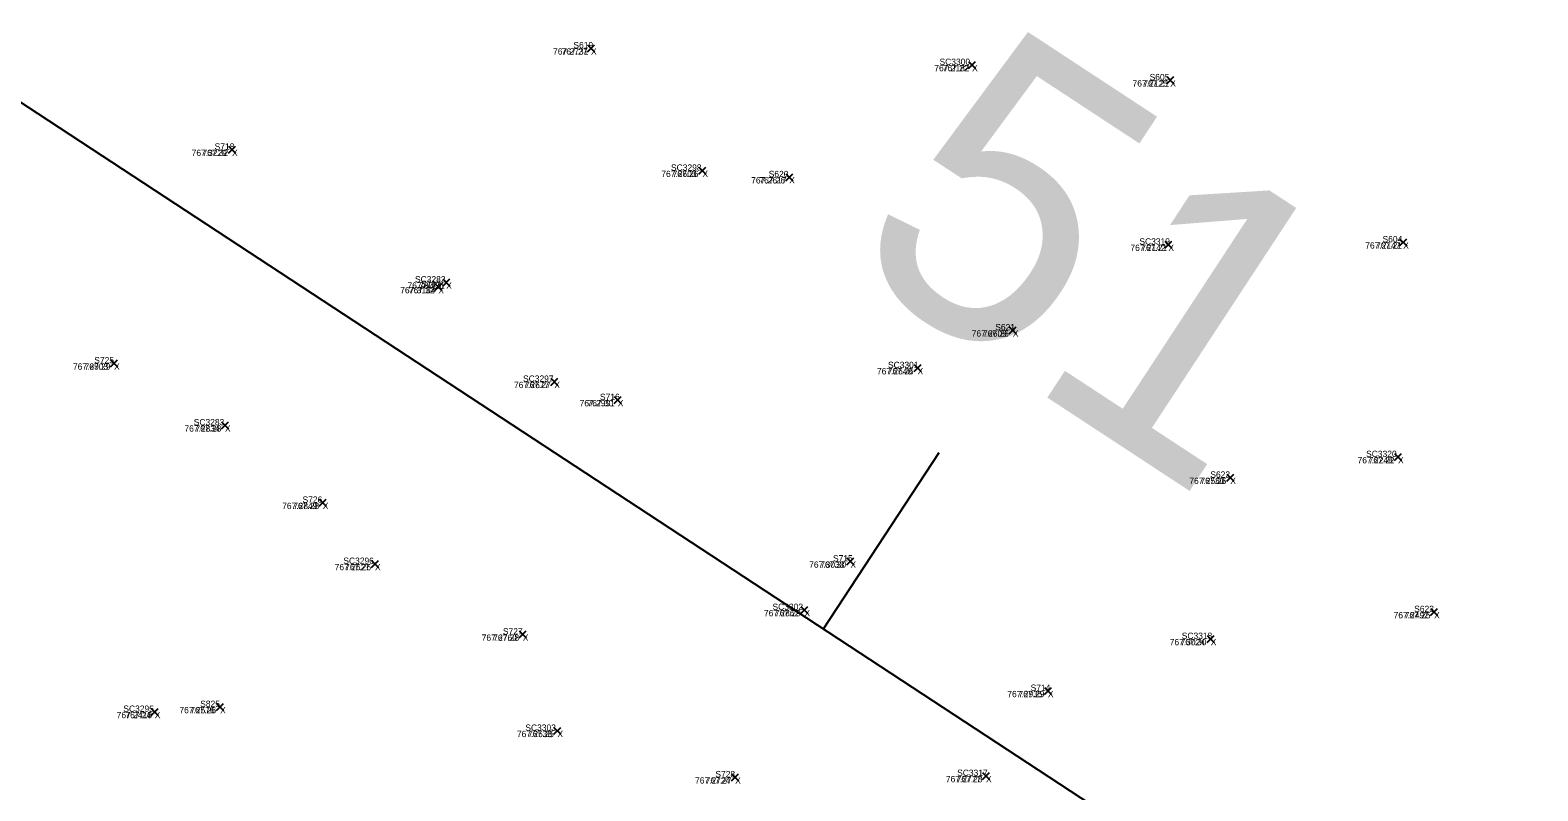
# Model space of a CAD drawing. Extents: x 1845019 to 1877956, y 680444 to 701081.
# Drawn here: x 1857724.6 to 1857738.9, y 694233.43 to 694240.65 of the extents above; entities that cross this region are included whole.
import ezdxf

# ---------------------------------------------------------------- set-up
doc = ezdxf.new("R2010")
doc.units = 0
for name, color, linetype in [('SV_X_CL_Survey_20', 7, 'Continuous'), ('SV_X_Random_Point', 7, 'Continuous'), ('SV_X_Text_Comment', 7, 'Continuous'), ('SV_X_Text_Elevation', 7, 'Continuous'), ('SV_X_Text_Name', 7, 'Continuous')]:
    doc.layers.add(name, color=color, linetype=linetype)

msp = doc.modelspace()

# ---------------------------------------------------------------- linework, layer by layer
at = {"layer": 'SV_X_CL_Survey_20'}
for p, q in [((1856038.267, 695346.314), (1858797.327, 693536.085)), ((1857732.122, 694234.97), (1857733.219, 694236.642))]:
    msp.add_line(p, q, dxfattribs=at)
at = {"layer": 'SV_X_Random_Point'}
for p, q in [((1857729.884, 694240.445), (1857729.95, 694240.512)), ((1857729.884, 694240.512), (1857729.95, 694240.445)), ((1857729.884, 694240.445), (1857729.95, 694240.512)), ((1857729.884, 694240.512), (1857729.95, 694240.445)), ((1857733.5, 694240.287), (1857733.566, 694240.354)), ((1857733.5, 694240.354), (1857733.566, 694240.287)), ((1857733.5, 694240.287), (1857733.566, 694240.354)), ((1857733.5, 694240.354), (1857733.566, 694240.287)), ((1857735.38, 694240.143), (1857735.447, 694240.21)), ((1857735.38, 694240.21), (1857735.447, 694240.143)), ((1857735.38, 694240.143), (1857735.447, 694240.21)), ((1857735.38, 694240.21), (1857735.447, 694240.143)), ((1857726.478, 694239.483), (1857726.544, 694239.55)), ((1857726.478, 694239.55), (1857726.544, 694239.483)), ((1857726.478, 694239.483), (1857726.544, 694239.55)), ((1857726.478, 694239.55), (1857726.544, 694239.483)), ((1857730.94, 694239.284), (1857731.007, 694239.35)), ((1857730.94, 694239.35), (1857731.007, 694239.284)), ((1857730.94, 694239.284), (1857731.007, 694239.35)), ((1857730.94, 694239.35), (1857731.007, 694239.284)), ((1857731.764, 694239.222), (1857731.831, 694239.289)), ((1857731.764, 694239.289), (1857731.831, 694239.222)), ((1857731.764, 694239.222), (1857731.831, 694239.289)), ((1857731.764, 694239.289), (1857731.831, 694239.222)), ((1857735.361, 694238.583), (1857735.428, 694238.649)), ((1857735.361, 694238.649), (1857735.428, 694238.583)), ((1857735.361, 694238.583), (1857735.428, 694238.649)), ((1857735.361, 694238.649), (1857735.428, 694238.583)), ((1857737.589, 694238.605), (1857737.656, 694238.671)), ((1857737.589, 694238.671), (1857737.656, 694238.605)), ((1857737.589, 694238.605), (1857737.656, 694238.671)), ((1857737.589, 694238.671), (1857737.656, 694238.605)), ((1857728.435, 694238.179), (1857728.502, 694238.246)), ((1857728.435, 694238.246), (1857728.502, 694238.179)), ((1857728.435, 694238.179), (1857728.502, 694238.246)), ((1857728.435, 694238.246), (1857728.502, 694238.179)), ((1857728.51, 694238.223), (1857728.577, 694238.29)), ((1857728.51, 694238.29), (1857728.577, 694238.223)), ((1857728.51, 694238.223), (1857728.577, 694238.29)), ((1857728.51, 694238.29), (1857728.577, 694238.223)), ((1857733.886, 694237.77), (1857733.952, 694237.836)), ((1857733.886, 694237.836), (1857733.952, 694237.77)), ((1857733.886, 694237.77), (1857733.952, 694237.836)), ((1857733.886, 694237.836), (1857733.952, 694237.77)), ((1857725.358, 694237.455), (1857725.425, 694237.522)), ((1857725.358, 694237.522), (1857725.425, 694237.455)), ((1857725.358, 694237.455), (1857725.425, 694237.522)), ((1857725.358, 694237.522), (1857725.425, 694237.455)), ((1857732.982, 694237.411), (1857733.049, 694237.477)), ((1857732.982, 694237.477), (1857733.049, 694237.411)), ((1857732.982, 694237.411), (1857733.049, 694237.477)), ((1857732.982, 694237.477), (1857733.049, 694237.411)), ((1857729.536, 694237.28), (1857729.603, 694237.347)), ((1857729.536, 694237.347), (1857729.603, 694237.28)), ((1857729.536, 694237.28), (1857729.603, 694237.347)), ((1857729.536, 694237.347), (1857729.603, 694237.28)), ((1857730.137, 694237.108), (1857730.204, 694237.175)), ((1857730.137, 694237.175), (1857730.204, 694237.108)), ((1857730.137, 694237.108), (1857730.204, 694237.175)), ((1857730.137, 694237.175), (1857730.204, 694237.108)), ((1857726.411, 694236.868), (1857726.477, 694236.935)), ((1857726.411, 694236.935), (1857726.477, 694236.868)), ((1857726.411, 694236.868), (1857726.477, 694236.935)), ((1857726.411, 694236.935), (1857726.477, 694236.868)), ((1857737.54, 694236.567), (1857737.607, 694236.634)), ((1857737.54, 694236.634), (1857737.607, 694236.567)), ((1857737.54, 694236.567), (1857737.607, 694236.634)), ((1857737.54, 694236.634), (1857737.607, 694236.567)), ((1857735.949, 694236.371), (1857736.015, 694236.437)), ((1857735.949, 694236.437), (1857736.015, 694236.371)), ((1857735.949, 694236.371), (1857736.015, 694236.437)), ((1857735.949, 694236.437), (1857736.015, 694236.371)), ((1857727.338, 694236.133), (1857727.405, 694236.2)), ((1857727.338, 694236.2), (1857727.405, 694236.133)), ((1857727.338, 694236.133), (1857727.405, 694236.2)), ((1857727.338, 694236.2), (1857727.405, 694236.133)), ((1857727.834, 694235.553), (1857727.901, 694235.619)), ((1857727.834, 694235.619), (1857727.901, 694235.553)), ((1857727.834, 694235.553), (1857727.901, 694235.619)), ((1857727.834, 694235.619), (1857727.901, 694235.553)), ((1857732.345, 694235.576), (1857732.412, 694235.642)), ((1857732.345, 694235.642), (1857732.412, 694235.576)), ((1857732.345, 694235.576), (1857732.412, 694235.642)), ((1857732.345, 694235.642), (1857732.412, 694235.576)), ((1857731.909, 694235.116), (1857731.975, 694235.183)), ((1857731.909, 694235.183), (1857731.975, 694235.116)), ((1857731.909, 694235.116), (1857731.975, 694235.183)), ((1857731.909, 694235.183), (1857731.975, 694235.116)), ((1857737.883, 694235.095), (1857737.949, 694235.162)), ((1857737.883, 694235.162), (1857737.949, 694235.095)), ((1857737.883, 694235.095), (1857737.949, 694235.162)), ((1857737.883, 694235.162), (1857737.949, 694235.095)), ((1857729.235, 694234.883), (1857729.302, 694234.95)), ((1857729.235, 694234.95), (1857729.302, 694234.883)), ((1857729.235, 694234.883), (1857729.302, 694234.95)), ((1857729.235, 694234.95), (1857729.302, 694234.883)), ((1857735.763, 694234.84), (1857735.83, 694234.907)), ((1857735.763, 694234.907), (1857735.83, 694234.84)), ((1857735.763, 694234.84), (1857735.83, 694234.907)), ((1857735.763, 694234.907), (1857735.83, 694234.84)), ((1857734.219, 694234.347), (1857734.286, 694234.414)), ((1857734.219, 694234.414), (1857734.286, 694234.347)), ((1857734.219, 694234.347), (1857734.286, 694234.414)), ((1857734.219, 694234.414), (1857734.286, 694234.347)), ((1857725.744, 694234.148), (1857725.811, 694234.215)), ((1857725.744, 694234.215), (1857725.811, 694234.148)), ((1857725.744, 694234.148), (1857725.811, 694234.215)), ((1857725.744, 694234.215), (1857725.811, 694234.148)), ((1857726.364, 694234.195), (1857726.431, 694234.261)), ((1857726.364, 694234.261), (1857726.431, 694234.195)), ((1857726.364, 694234.195), (1857726.431, 694234.261)), ((1857726.364, 694234.261), (1857726.431, 694234.195)), ((1857729.565, 694233.969), (1857729.631, 694234.035)), ((1857729.565, 694234.035), (1857729.631, 694233.969)), ((1857729.565, 694233.969), (1857729.631, 694234.035)), ((1857729.565, 694234.035), (1857729.631, 694233.969)), ((1857731.251, 694233.528), (1857731.318, 694233.594)), ((1857731.251, 694233.594), (1857731.318, 694233.528)), ((1857731.251, 694233.528), (1857731.318, 694233.594)), ((1857731.251, 694233.594), (1857731.318, 694233.528)), ((1857733.632, 694233.54), (1857733.699, 694233.607)), ((1857733.632, 694233.607), (1857733.699, 694233.54)), ((1857733.632, 694233.54), (1857733.699, 694233.607)), ((1857733.632, 694233.607), (1857733.699, 694233.54))]:
    msp.add_line(p, q, dxfattribs=at)

# ---------------------------------------------------------------- texts
at = {"layer": 'SV_X_CL_Survey_20'}
msp.add_text('51', height=2.8, rotation=326.731, dxfattribs=at).set_placement((1857732.267, 694238.463))
at = {"layer": 'SV_X_Text_Comment'}
for p in [(1857729.917, 694240.419), (1857733.533, 694240.261), (1857735.413, 694240.116), (1857726.511, 694239.457), (1857730.974, 694239.257), (1857731.797, 694239.196), (1857735.395, 694238.556), (1857737.623, 694238.578), (1857728.469, 694238.153), (1857728.543, 694238.197), (1857733.919, 694237.743), (1857725.392, 694237.429), (1857733.015, 694237.384), (1857729.569, 694237.254), (1857730.171, 694237.081), (1857726.444, 694236.841), (1857737.574, 694236.54), (1857735.982, 694236.344), (1857727.372, 694236.106), (1857727.868, 694235.526), (1857732.378, 694235.549), (1857731.942, 694235.089), (1857737.916, 694235.069), (1857729.269, 694234.856), (1857735.797, 694234.814), (1857734.252, 694234.321), (1857725.778, 694234.122), (1857726.398, 694234.168), (1857729.598, 694233.942), (1857731.285, 694233.501), (1857733.665, 694233.514)]:
    msp.add_text('X', height=0.06, dxfattribs=at).set_placement(p)
at = {"layer": 'SV_X_Text_Elevation'}
for s, p in [('767.2731', (1857729.557, 694240.419)), ('767.27', (1857729.638, 694240.419)), ('767.2182', (1857733.174, 694240.261)), ('767.22', (1857733.254, 694240.261)), ('767.2125', (1857735.055, 694240.116)), ('767.21', (1857735.157, 694240.116)), ('767.3229', (1857726.128, 694239.457)), ('767.32', (1857726.23, 694239.457)), ('767.2603', (1857730.584, 694239.257)), ('767.26', (1857730.691, 694239.257)), ('767.2617', (1857731.437, 694239.196)), ('767.26', (1857731.514, 694239.196)), ('767.2142', (1857735.035, 694238.556)), ('767.21', (1857735.138, 694238.556)), ('767.2147', (1857737.263, 694238.578)), ('767.21', (1857737.366, 694238.578)), ('767.3164', (1857728.107, 694238.153)), ('767.3051', (1857728.176, 694238.197)), ('767.32', (1857728.188, 694238.153)), ('767.31', (1857728.285, 694238.197)), ('767.2609', (1857733.529, 694237.743)), ('767.26', (1857733.636, 694237.743)), ('767.2903', (1857725.002, 694237.429)), ('767.29', (1857725.112, 694237.429)), ('767.2648', (1857732.63, 694237.384)), ('767.26', (1857732.732, 694237.384)), ('767.2677', (1857729.186, 694237.254)), ('767.27', (1857729.29, 694237.254)), ('767.2991', (1857729.809, 694237.081)), ('767.30', (1857729.884, 694237.081)), ('767.2834', (1857726.06, 694236.841)), ('767.28', (1857726.164, 694236.841)), ('767.2248', (1857737.19, 694236.54)), ('767.22', (1857737.295, 694236.54)), ('767.2580', (1857735.594, 694236.344)), ('767.26', (1857735.699, 694236.344)), ('767.2849', (1857726.987, 694236.106)), ('767.28', (1857727.092, 694236.106)), ('767.2627', (1857727.485, 694235.526)), ('767.26', (1857727.585, 694235.526)), ('767.3033', (1857731.987, 694235.549)), ('767.30', (1857732.092, 694235.549)), ('767.2862', (1857731.558, 694235.089)), ('767.29', (1857731.662, 694235.089)), ('767.2492', (1857737.532, 694235.069)), ('767.25', (1857737.637, 694235.069)), ('767.2760', (1857728.88, 694234.856)), ('767.28', (1857728.989, 694234.856)), ('767.3024', (1857735.408, 694234.814)), ('767.30', (1857735.511, 694234.814)), ('767.2935', (1857733.867, 694234.321)), ('767.29', (1857733.973, 694234.321)), ('767.2418', (1857725.417, 694234.122)), ('767.24', (1857725.499, 694234.122)), ('767.2576', (1857726.012, 694234.168)), ('767.26', (1857726.115, 694234.168)), ('767.2538', (1857729.214, 694233.942)), ('767.25', (1857729.319, 694233.942)), ('767.2724', (1857730.904, 694233.501)), ('767.27', (1857731.005, 694233.501)), ('767.2777', (1857733.284, 694233.514)), ('767.28', (1857733.386, 694233.514))]:
    msp.add_text(s, height=0.06, dxfattribs=at).set_placement(p)
at = {"layer": 'SV_X_Text_Name'}
for s, p in [('S619', (1857729.75, 694240.479)), ('S619', (1857729.75, 694240.479)), ('SC3300', (1857733.224, 694240.321)), ('SC3300', (1857733.224, 694240.321)), ('S605', (1857735.217, 694240.176)), ('S605', (1857735.217, 694240.176)), ('S718', (1857726.346, 694239.517)), ('S718', (1857726.346, 694239.517)), ('SC3298', (1857730.676, 694239.317)), ('SC3298', (1857730.676, 694239.317)), ('S620', (1857731.603, 694239.256)), ('S620', (1857731.603, 694239.256)), ('SC3319', (1857735.12, 694238.616)), ('SC3319', (1857735.12, 694238.616)), ('S604', (1857737.427, 694238.638)), ('S604', (1857737.427, 694238.638)), ('SC3282', (1857728.247, 694238.257)), ('SC3282', (1857728.247, 694238.257)), ('S717', (1857728.304, 694238.213)), ('S717', (1857728.304, 694238.213)), ('S621', (1857733.752, 694237.803)), ('S621', (1857733.753, 694237.803)), ('S725', (1857725.204, 694237.489)), ('S725', (1857725.204, 694237.489)), ('SC3301', (1857732.734, 694237.444)), ('SC3301', (1857732.735, 694237.444)), ('SC3297', (1857729.272, 694237.314)), ('SC3297', (1857729.272, 694237.314)), ('S716', (1857730.002, 694237.141)), ('S716', (1857730.002, 694237.141)), ('SC3283', (1857726.148, 694236.901)), ('SC3283', (1857726.148, 694236.901)), ('SC3320', (1857737.271, 694236.6)), ('SC3320', (1857737.271, 694236.6)), ('S622', (1857735.793, 694236.404)), ('S622', (1857735.793, 694236.404)), ('S726', (1857727.18, 694236.166)), ('S726', (1857727.18, 694236.166)), ('SC3296', (1857727.567, 694235.586)), ('SC3296', (1857727.567, 694235.586)), ('S715', (1857732.213, 694235.609)), ('S715', (1857732.213, 694235.609)), ('SC3302', (1857731.639, 694235.149)), ('SC3302', (1857731.639, 694235.149)), ('S623', (1857737.727, 694235.129)), ('S623', (1857737.727, 694235.129)), ('S727', (1857729.081, 694234.916)), ('S727', (1857729.081, 694234.916)), ('SC3318', (1857735.522, 694234.874)), ('SC3318', (1857735.522, 694234.874)), ('S714', (1857734.088, 694234.381)), ('S714', (1857734.088, 694234.381)), ('SC3295', (1857725.48, 694234.182)), ('SC3295', (1857725.48, 694234.182)), ('S825', (1857726.209, 694234.228)), ('S825', (1857726.209, 694234.228)), ('SC3303', (1857729.294, 694234.002)), ('SC3303', (1857729.294, 694234.002)), ('S728', (1857731.097, 694233.561)), ('S728', (1857731.097, 694233.561)), ('SC3317', (1857733.391, 694233.574)), ('SC3317', (1857733.391, 694233.574))]:
    msp.add_text(s, height=0.06, dxfattribs=at).set_placement(p)

doc.saveas('drawing.dxf')
